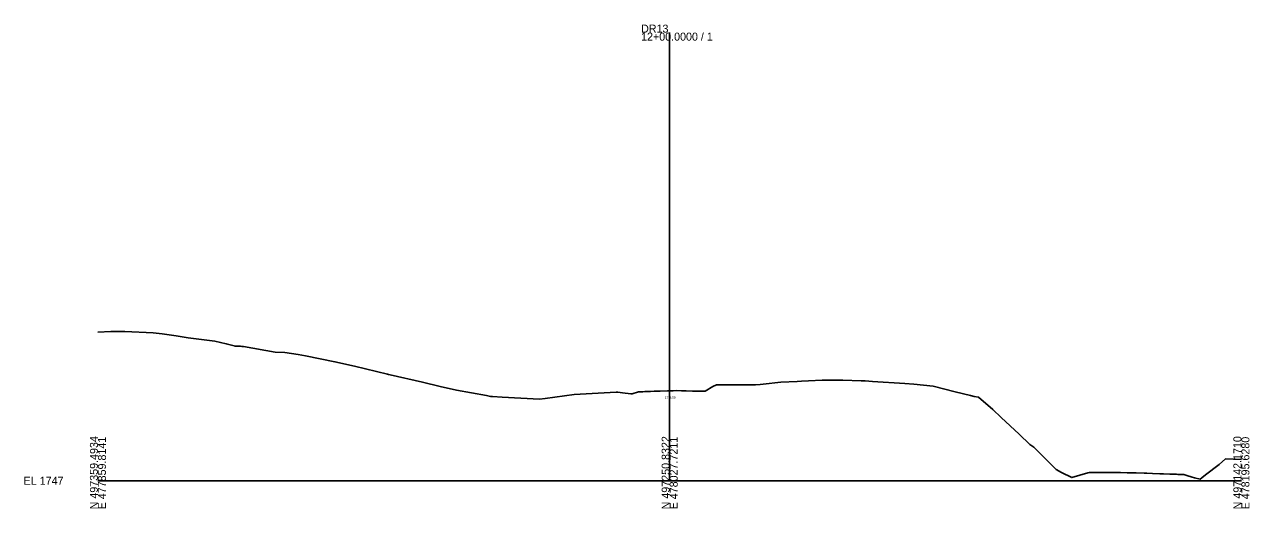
# Model space of a CAD drawing. Extents: x -26 to 403, y -10 to 2160.
# Drawn here: x -25.7 to 402.8, y 1990.3 to 2159.5 of the extents above; entities that cross this region are included whole.
import ezdxf

# ---------------------------------------------------------------- set-up
doc = ezdxf.new("R2010")
doc.units = 0
for name, color, linetype in [('Exist Cross Section Cell', 7, 'Continuous'), ('Exist XS Center Line Elevation Label', 7, 'Continuous'), ('Exist XS Ground Line', 7, 'Continuous'), ('Scratch_Level_5', 7, 'Continuous')]:
    doc.layers.add(name, color=color, linetype=linetype)

msp = doc.modelspace()

# ---------------------------------------------------------------- linework, layer by layer
at = {"layer": 'Exist Cross Section Cell'}
for p, q in [((200, 2000), (200, 2156.71)), ((0, 2000), (200, 2000)), ((200, 2000), (400, 2000))]:
    msp.add_line(p, q, dxfattribs=at)
at = {"layer": 'Exist XS Ground Line'}
msp.add_lwpolyline([(0, 2052.02), (4.52, 2052.21), (9.43, 2052.24), (19.33, 2051.77), (22.41, 2051.38), (27.35, 2050.67), (31.54, 2050.04), (40.86, 2048.85), (44.88, 2047.89), (48.07, 2047.08), (48.49, 2047.06), (48.87, 2047.05), (49.82, 2047.02), (50.31, 2047), (50.86, 2046.98), (62.05, 2045.02), (65.33, 2044.87), (70.04, 2044.1), (72.56, 2043.7), (77.79, 2042.64), (82.9, 2041.62), (89.7, 2040.09), (101.31, 2037.28), (101.61, 2037.2), (102.18, 2037.07), (113.53, 2034.44), (119.72, 2032.94), (125.44, 2031.7), (135.94, 2029.77), (137.36, 2029.5), (138.07, 2029.44), (141.39, 2029.24), (154.51, 2028.5), (156.5, 2028.78), (166.59, 2030.14), (181.34, 2030.96), (181.88, 2030.99), (183.55, 2030.78), (186.45, 2030.44), (186.86, 2030.39), (189.04, 2031.13), (189.44, 2031.14), (190.63, 2031.15), (191.37, 2031.16), (192.08, 2031.17), (192.44, 2031.18), (193.32, 2031.21), (194.62, 2031.3), (196.3, 2031.38), (196.65, 2031.39), (199.27, 2031.48), (199.85, 2031.49), (201.21, 2031.5), (202.23, 2031.51), (204.09, 2031.46), (205.43, 2031.43), (205.8, 2031.41), (208.03, 2031.32), (208.79, 2031.31), (209.13, 2031.3), (209.96, 2031.33), (212.38, 2031.3), (215.06, 2032.95), (216.42, 2033.51), (230, 2033.59), (231.69, 2033.62), (232.67, 2033.74), (238.92, 2034.45), (244.58, 2034.73), (246.15, 2034.81), (248.58, 2034.94), (253.39, 2035.2), (256.49, 2035.14), (260.62, 2035.13), (266.99, 2034.95), (268.41, 2034.89), (271, 2034.73), (282.32, 2034.07), (285.4, 2033.77), (292.23, 2033.06), (299.93, 2031.15), (305.29, 2029.83), (306.57, 2029.46), (308.02, 2029.18), (313.08, 2024.92), (316.02, 2022.07), (322.29, 2016.3), (325.95, 2012.72), (327.44, 2011.72), (335.21, 2003.91), (337.1, 2002.95), (340.74, 2001.14), (346.34, 2002.8), (346.79, 2002.95), (348.33, 2002.94), (349.31, 2002.92), (350.33, 2002.9), (351.12, 2002.89), (353.09, 2002.87), (353.69, 2002.86), (354.07, 2002.86), (355.92, 2002.85), (357.07, 2002.84), (357.68, 2002.84), (360.05, 2002.81), (361, 2002.8), (362.29, 2002.79), (363.14, 2002.78), (366, 2002.68), (366.89, 2002.65), (368.96, 2002.57), (371.49, 2002.48), (371.95, 2002.46), (372.77, 2002.43), (374.92, 2002.34), (375.96, 2002.31), (377.28, 2002.27), (377.75, 2002.25), (379.16, 2002.21), (379.88, 2002.18), (380.86, 2001.89), (382.82, 2001.31), (383.63, 2001.08), (385.59, 2000.52), (386.2, 2001.08), (387.45, 2002.08), (392.19, 2005.74), (394.45, 2007.67), (400, 2007.48)], dxfattribs=at)
at = {"layer": 'Scratch_Level_5'}
msp.add_lwpolyline([(47.86, 2047.08), (50.86, 2046.98), (62.05, 2045.02), (65.33, 2044.87), (70.04, 2044.1), (72.56, 2043.7), (77.79, 2042.64), (82.9, 2041.62), (89.7, 2040.09), (101.31, 2037.28), (101.61, 2037.2), (102.18, 2037.07), (113.53, 2034.44), (119.72, 2032.94), (125.44, 2031.7), (135.94, 2029.77), (137.36, 2029.5), (138.07, 2029.44), (141.39, 2029.24), (154.51, 2028.5), (156.5, 2028.78), (166.59, 2030.14), (181.34, 2030.96), (181.88, 2030.99), (183.55, 2030.78), (186.45, 2030.44), (186.86, 2030.39), (189.04, 2031.13), (189.44, 2031.14), (190.63, 2031.15), (191.37, 2031.16), (192.08, 2031.17), (192.44, 2031.18), (193.32, 2031.21), (194.62, 2031.3), (196.3, 2031.38), (196.65, 2031.39), (199.27, 2031.48), (199.85, 2031.49), (201.21, 2031.5), (202.23, 2031.51), (204.09, 2031.46), (205.43, 2031.43), (205.8, 2031.41), (208.03, 2031.32), (208.79, 2031.31), (209.13, 2031.3), (209.96, 2031.33), (212.38, 2031.3), (215.06, 2032.95), (216.42, 2033.51), (230, 2033.59), (231.69, 2033.62), (232.67, 2033.74), (238.92, 2034.45), (244.58, 2034.73), (246.15, 2034.81), (248.58, 2034.94), (253.39, 2035.2), (256.49, 2035.14), (260.62, 2035.13), (266.99, 2034.95), (268.41, 2034.89), (271, 2034.73), (282.32, 2034.07), (285.4, 2033.77), (292.23, 2033.06), (299.93, 2031.15), (305.29, 2029.83), (306.57, 2029.46), (308.02, 2029.18), (313.08, 2024.92), (316.02, 2022.07), (322.29, 2016.3), (325.95, 2012.72), (327.44, 2011.72), (335.21, 2003.91), (337.1, 2002.95), (340.74, 2001.14), (346.34, 2002.8), (346.79, 2002.95), (348.33, 2002.94), (349.31, 2002.92), (350.33, 2002.9), (351.12, 2002.89), (353.09, 2002.87), (353.69, 2002.86), (354.07, 2002.86), (355.92, 2002.85), (357.07, 2002.84), (357.68, 2002.84), (360.05, 2002.81), (361, 2002.8), (362.29, 2002.79), (363.14, 2002.78), (366, 2002.68), (366.89, 2002.65), (368.96, 2002.57), (371.49, 2002.48), (371.95, 2002.46), (372.77, 2002.43), (374.92, 2002.34), (375.96, 2002.31), (377.28, 2002.27), (377.75, 2002.25), (379.16, 2002.21), (379.88, 2002.18), (380.86, 2001.89), (382.82, 2001.31), (383.63, 2001.08), (385.59, 2000.52), (386.2, 2001.08), (387.45, 2002.08), (392.19, 2005.74), (394.45, 2007.67), (400, 2007.48)], dxfattribs=at)

# ---------------------------------------------------------------- texts
at = {"layer": 'Exist Cross Section Cell'}
for s, p in [('12+00.0000 / 1', (190, 2153.91)), ('DR13', (190, 2156.71)), ('EL 1747', (-26, 1998.6))]:
    msp.add_text(s, height=2.8, dxfattribs=at).set_placement(p)
for s, p in [('N 497359.4934', (0, 1990)), ('E 477859.8141', (2.8, 1990)), ('N 497250.8322', (200, 1990)), ('E 478027.7211', (202.8, 1990)), ('N 497142.1710', (400, 1990)), ('E 478195.6280', (402.8, 1990))]:
    msp.add_text(s, height=2.8, rotation=90, dxfattribs=at).set_placement(p)
at = {"layer": 'Exist XS Center Line Elevation Label'}
msp.add_text('1778.50', height=0.75, dxfattribs=at).set_placement((198.28, 2028.75))

doc.saveas('drawing.dxf')
